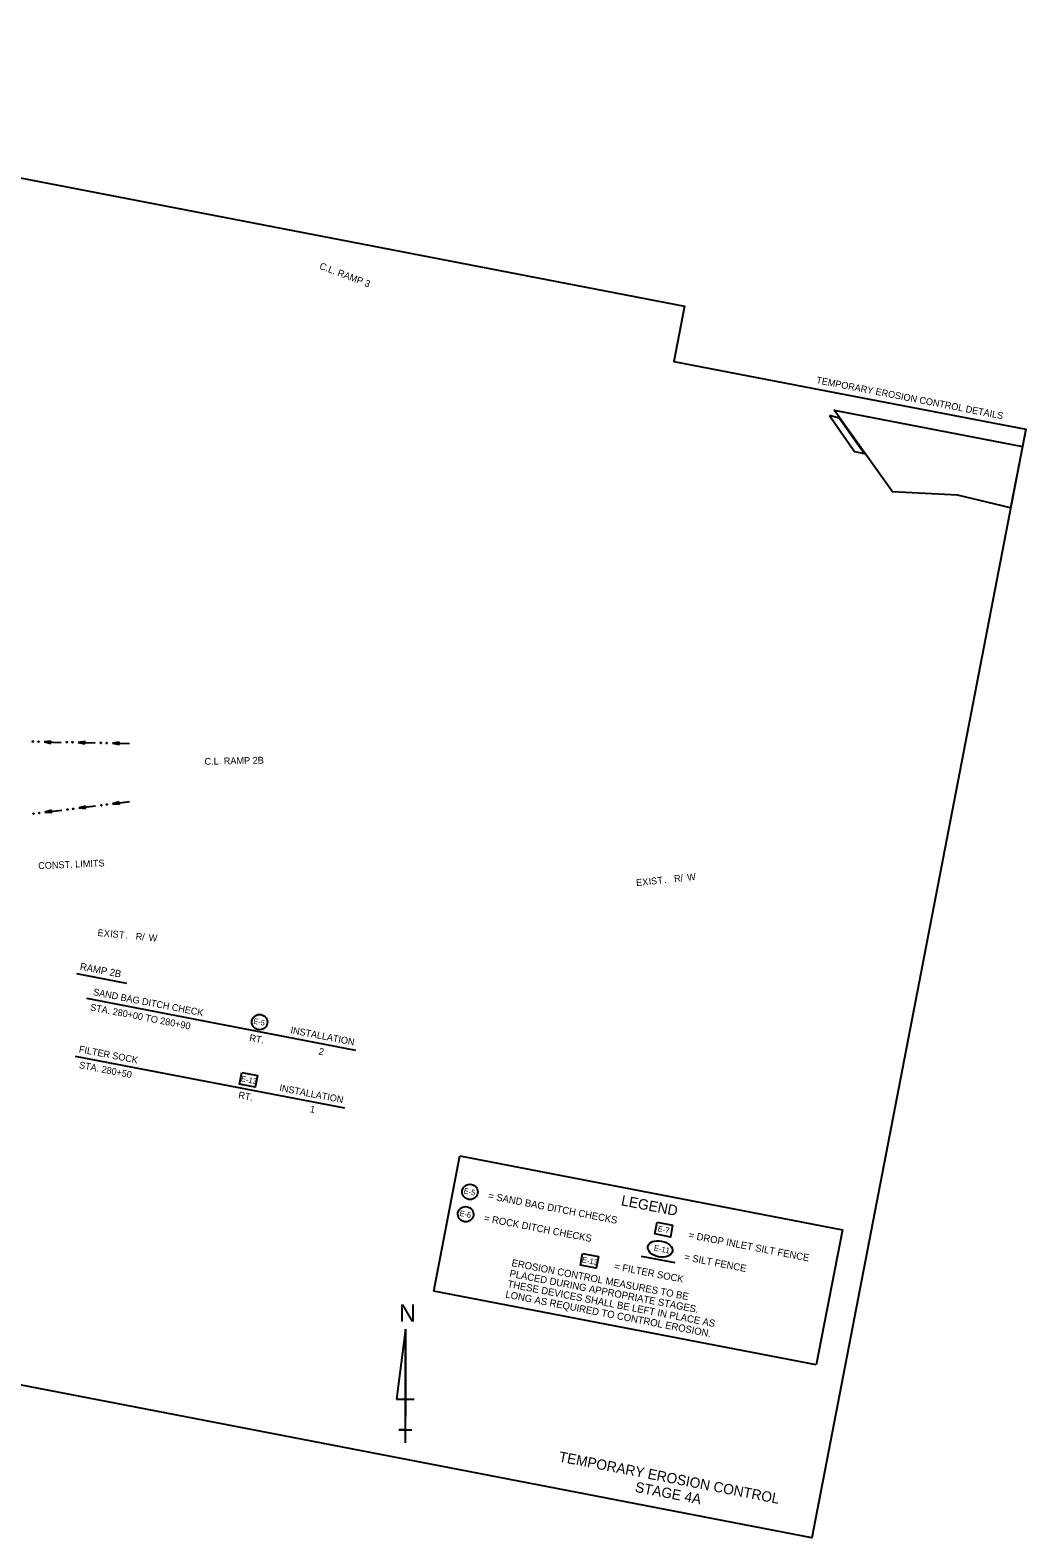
# Model space of a CAD drawing. Extents: x 607205 to 611729, y 416008 to 419873.
# Drawn here: x 610853 to 611729, y 418547 to 419873 of the extents above; entities that cross this region are included whole.
import ezdxf

# ---------------------------------------------------------------- set-up
doc = ezdxf.new("R2010")
doc.units = 0
for name, color, linetype in [('Default', 7, 'Continuous'), ('G-ANNO-TEXT', 7, 'Continuous'), ('Level 1', 7, 'Continuous'), ('Level 43', 7, 'Continuous'), ('Level 44', 7, 'Continuous'), ('R_Draft', 7, 'Continuous'), ('TP_Mask', 7, 'Continuous'), ('X_ARROWS_LEGEND', 7, 'Continuous')]:
    doc.layers.add(name, color=color, linetype=linetype)

msp = doc.modelspace()

# ---------------------------------------------------------------- linework, layer by layer
at = {"layer": 'G-ANNO-TEXT'}
for p, q in [((610894.1, 419043.7), (610937.9, 419035.2)), ((610902.9, 419022.1), (611139.5, 418976.4)), ((610893, 418971.2), (611129.7, 418925.5))]:
    msp.add_line(p, q, dxfattribs=at)
at = {"layer": 'Level 43'}
for p, q in [((610871.6, 419248.2), (610865.6, 419247.4)), ((610865.6, 419247.4), (610880.6, 419246.8)), ((610865.6, 419247.4), (610871.5, 419246.1)), ((610871.5, 419246.1), (610871.6, 419248.2)), ((610880.6, 419247.4), (610880.5, 419247.4)), ((610901.6, 419247.9), (610895.6, 419247)), ((610895.6, 419247), (610910.6, 419246.6)), ((610895.6, 419247), (610901.5, 419245.8)), ((610901.5, 419245.8), (610901.6, 419247.9)), ((610910.6, 419246.7), (610910.5, 419246.7)), ((610931.6, 419247.3), (610925.6, 419246.4)), ((610925.6, 419246.4), (610940.6, 419246.1)), ((610925.6, 419246.4), (610931.5, 419245.2)), ((610931.5, 419245.2), (610931.6, 419247.3)), ((610925.8, 419193), (610940.7, 419194.9)), ((610931.6, 419194.8), (610925.8, 419193)), ((610925.8, 419193), (610931.9, 419192.7)), ((610931.9, 419192.7), (610931.6, 419194.8)), ((610866.3, 419185.5), (610881.2, 419187.3)), ((610872.1, 419187.3), (610866.3, 419185.5)), ((610866.3, 419185.5), (610872.4, 419185.2)), ((610872.4, 419185.2), (610872.1, 419187.3)), ((610881.1, 419187.4), (610881.1, 419187.4)), ((610896, 419189.3), (610910.9, 419191.1)), ((610901.9, 419191), (610896, 419189.3)), ((610896, 419189.3), (610902.1, 419188.9)), ((610902.1, 419188.9), (610901.9, 419191)), ((610910.9, 419191.1), (610910.9, 419191.1))]:
    msp.add_line(p, q, dxfattribs=at)
for centre in [(610855.6, 419247.8), (610860.6, 419247.6), (610885.6, 419247.2), (610890.6, 419247.1), (610915.5, 419246.5), (610920.6, 419246.4), (610915.9, 419191.7), (610920.8, 419192.3), (610856.3, 419184.3), (610861.3, 419184.9), (610886.1, 419188), (610891.1, 419188.6)]:
    msp.add_circle(centre, 0.375, dxfattribs=at)
at = {"layer": 'Level 44'}
msp.add_lwpolyline([(611390.6, 418795.3), (611420.2, 418789.6)], dxfattribs=at)
at = {"layer": 'TP_Mask'}
for points in [[(610171.9, 419873.3), (611428.7, 419630.7), (611419.3, 419582), (611533.5, 419560), (611729, 419522.3), (611726, 419507.1), (611540.8, 418547.5), (609974.4, 418849.9)], [(611726, 419507.1), (611715.6, 419453.2), (611668.9, 419464.5), (611611.7, 419467.4), (611560.4, 419539)], [(611556.3, 419534.4), (611578.4, 419502.9), (611586.7, 419501), (611564.9, 419532.1)]]:
    msp.add_lwpolyline(points, close=True, dxfattribs=at)
at = {"layer": 'X_ARROWS_LEGEND'}
for p, q in [((611208.2, 418764.5), (611231.2, 418883.3)), ((611231.2, 418883.3), (611567.6, 418818.4)), ((611567.6, 418818.4), (611544.7, 418699.5)), ((611544.7, 418699.5), (611208.2, 418764.5)), ((611183.3, 418731), (611175.6, 418669.5)), ((611183.3, 418631), (611183.3, 418731)), ((611183.3, 418731), (611183.3, 418654.1)), ((611175.6, 418669.5), (611191, 418669.5)), ((611183.3, 418631), (611183.3, 418654.1)), ((611183.3, 418642.6), (611177.6, 418642.6)), ((611177.6, 418642.6), (611189.1, 418642.6)), ((611183.3, 418631), (611183.3, 418642.6))]:
    msp.add_line(p, q, dxfattribs=at)
for points in [[(611039.4, 418956.7), (611053.2, 418954), (611051.2, 418943.7), (611037.4, 418946.4)], [(611404.6, 418825), (611418.3, 418822.4), (611416.4, 418812), (611402.6, 418814.7)], [(611339.2, 418797.6), (611353, 418794.9), (611351, 418784.6), (611337.3, 418787.2)]]:
    msp.add_lwpolyline(points, close=True, dxfattribs=at)
for centre, major_axis, ratio in [((611055.1, 419001), (-6.76, 1.31), 0.97521), ((611240.1, 418851.7), (-6.76, 1.31), 0.97521), ((611236.3, 418832.1), (-6.76, 1.31), 0.97521), ((611407.3, 418801.6), (10.8, -2.1), 0.638788)]:
    msp.add_ellipse(centre, major_axis=major_axis, ratio=ratio, dxfattribs=at)

# ---------------------------------------------------------------- texts
at = {"layer": 'Default'}
for s, rotation, p in [('C.L. RAMP 3', 339.2097, (611107.2, 419663.6)), ('C.L. RAMP 2B', 1.1692, (611006.7, 419227.3))]:
    msp.add_text(s, height=6, rotation=rotation, dxfattribs=at).set_placement(p)
at = {"layer": 'G-ANNO-TEXT'}
for s, height, p in [('TEMPORARY EROSION CONTROL DETAILS', 6, (611544.3, 419562.8)), ('RAMP 2B', 6.25, (610896.7, 419047.1)), ('SAND BAG DITCH CHECK', 6, (610908.3, 419024.8)), ('STA. 280+00 TO 280+90', 6, (610905.7, 419011.4)), ('INSTALLATION ', 6, (611081.9, 418991.3)), ('FILTER SOCK', 6, (610895.8, 418974.5)), ('RT. ', 6, (611045.7, 418984.5)), ('STA. 280+50', 6, (610895.9, 418960.6)), ('2', 6, (611106.7, 418972.6)), ('RT. ', 6, (611036, 418934.2)), ('INSTALLATION ', 6, (611072.1, 418940.5)), ('1', 6, (611098.9, 418921.9)), ('TEMPORARY EROSION CONTROL ', 9, (611317.7, 418614.7)), ('STAGE 4A', 9, (611384.8, 418588))]:
    msp.add_text(s, height=height, rotation=349.0745, dxfattribs=at).set_placement(p)
at = {"layer": 'Level 1'}
for s, p in [('= DROP INLET SILT FENCE', (611431.9, 418811)), ('= SILT FENCE', (611428.1, 418791.7)), ('= FILTER SOCK', (611366.5, 418783.5))]:
    msp.add_text(s, height=6.25, rotation=349.0745, dxfattribs=at).set_placement(p)
at = {"layer": 'R_Draft'}
for s, rotation, p in [('CONST. LIMITS', 2.4647, (610860.5, 419135.5)), ('E', 5.9666, (611386.5, 419120.6)), ('X', 5.9666, (611391.9, 419121.1)), ('I', 5.9666, (611397.6, 419121.7)), ('S', 5.9666, (611399.6, 419121.9)), ('T', 5.9666, (611405.2, 419122.5)), ('R', 5.9666, (611419.9, 419124.1)), ('/', 5.9666, (611425.5, 419124.7)), ('W', 5.9666, (611431.4, 419125.3)), ('.', 5.9666, (611411, 419123.1)), ('E', 354.5081, (610912.4, 419076.8)), ('X', 354.5081, (610917.8, 419076.3)), ('I', 354.5081, (610923.5, 419075.7)), ('S', 354.5081, (610925.5, 419075.6)), ('T', 354.5081, (610931.2, 419075)), ('.', 354.5081, (610937, 419074.5)), ('R', 354.5081, (610945.9, 419073.6)), ('/', 354.5081, (610951.5, 419073.1)), ('W', 354.5081, (610957.3, 419072.5))]:
    msp.add_text(s, height=6, rotation=rotation, dxfattribs=at).set_placement(p)
at = {"layer": 'X_ARROWS_LEGEND'}
for s, height, rotation, p in [('E-5', 4.88, 349.0745, (611049.3, 418999.7)), ('E-13', 5, 348.6922, (611038.4, 418949)), ('E-5', 4.88, 349.0745, (611234.3, 418850.4)), ('= SAND BAG DITCH CHECKS', 6.25, 349.0745, (611255.8, 418845.5)), ('LEGEND', 9.14, 349.0745, (611372.5, 418840)), ('E-6', 4.88, 349.0745, (611230.6, 418830.7)), ('= ROCK DITCH CHECKS', 6.25, 349.0745, (611252, 418825.9)), ('E-7', 5, 348.6922, (611404.8, 418817.1)), ('E-13', 5, 348.6922, (611338.2, 418789.9)), ('E-11', 5, 349.0745, (611401.5, 418800.2)), ('PLACED DURING APPROPRIATE STAGES. ', 6.25, 349.0745, (611274.5, 418777.2)), ('EROSION CONTROL MEASURES TO BE', 6.25, 349.0745, (611276.3, 418786.5)), ('THESE DEVICES SHALL BE LEFT IN PLACE AS ', 6.25, 349.0745, (611272.7, 418768)), ('LONG AS REQUIRED TO CONTROL EROSION.', 6.25, 349.0745, (611270.9, 418758.8)), ('N', 15.4, 360, (611177.7, 418737.5))]:
    msp.add_text(s, height=height, rotation=rotation, dxfattribs=at).set_placement(p)

doc.saveas('drawing.dxf')
